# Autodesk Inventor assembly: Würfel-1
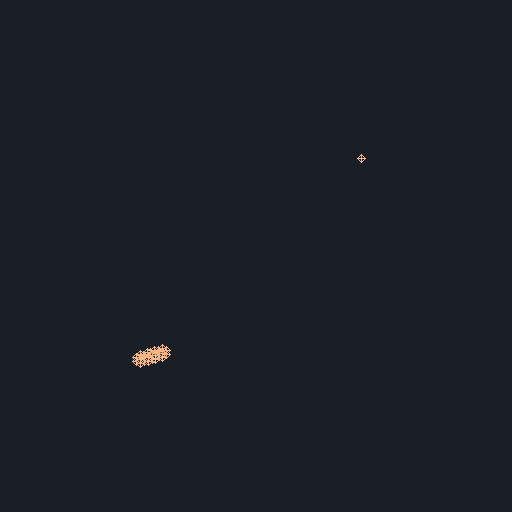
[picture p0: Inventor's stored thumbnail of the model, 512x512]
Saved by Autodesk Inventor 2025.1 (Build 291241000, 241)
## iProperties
Company: Ed. Züblin AG
Created: 2021-07
Part Number: Würfel-1
Material: Stahlbeton C30/37
Document SubType Name: Assembly
Designer: Eimannsmir
Mass: 14.8261 g
Surface Area: 31.3494 cm^2
Volume: 5.93044 cm^3
Density: 2.5 g/cm^3
z_Bereich: Tunnelbau
z_Direktion: Tief- und Tunnelbau
z_Konzerneinheit: Zentrale Technik
cpiComponentType: Attribut
cpiFitMatchkey: =<z_Matchkey>
z_Matchkey: =<z_Matchkey_010>_<z_Matchkey_020>_<z_Matchkey_030>_<z_Matchkey_040>_<z_Matchkey_050>_<z_Matchkey_060>_<z_Matchkey_070>_<z_Matchkey_080>_<z_Matchkey_090>_<z_Mat
z_Matchkey_010: xxxxx
z_Matchkey_020: 5DTUB
z_Matchkey_030: xxx
z_Matchkey_040: xxx
z_Matchkey_050: xxx
z_Matchkey_060: xxx
z_Matchkey_070: xxx
z_Matchkey_080: xxx
z_Matchkey_090: xxx
z_Matchkey_100: xxx
z_Matchkey_110: xxx
z_Matchkey_120: xxxxxxx
z_Matchkey_130: xxxx
z_Matchkey_140: xxxx
DocNumber: Würfel-1.iam
Folder: Übung\
VDS_Category: Konstruktion
Koordinate x - Ursprung: 0.0
Koordinate y - Ursprung: 0.0
Koordinate z - Ursprung: 0.0
Rotation - z-Achse: 0.0
Betondeckung: ND
Betonstahlguete: ND
Bewehrungsgehalt: ND
Druckfestigkeitsklasse: ND
Expositionsklasse_X: ND
Expositionsklasse_XA: ND
Expositionsklasse_XC: ND
Expositionsklasse_XD: ND
Expositionsklasse_XF: ND
Expositionsklasse_XM: ND
Expositionsklasse_XS: ND
Feuchtigkeitsklasse: ND
Groesstkorn: ND
Herstellungsort: ND
Luftporenbeton: ND
Rohdichte: ND
Sichtbetonklasse: ND
Unbewehrter_Beton: ND
Wasserzementwert_max: ND
WU_Beton: ND
Zusatzmittel: ND
010_Eigentuemer: ND
020_Autor: ND
030_Projektnummer: ND
040_Bereich: ND
050_Vertragspartner: ND
060_Gewerk: ND
070_Bauwerk: ND
080_Bauwerksnummer: ND
090_Bezeichnung: ND
100_Gruppe: ND
110_Element: ND
120_Elementtyp: ND
130_Identifikationsnummer: ND
140_Position_1: ND
150_Position_2: ND
160_PUID: ND
170_Hauptmaterialitaet: ND
171_Materialindikator_1: ND
172_Materialindikator_2: ND
Dicke: ND
Flaeche: ND
Streckenachse: ND
Streckenkilometer_Anfang: ND
Streckenkilometer_Ende: ND
Tunnelachse: ND
Tunnelmeter_Anfang: ND
Tunnelmeter_Ende: ND
4D_Vorgangs_ID: ND
Bauphase_Abgebrochen: ND
Bauphase_Erstellt: ND
Status: ND
Author: Eimannsmir
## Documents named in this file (2)
- C:\z_Vault\CAD\Übung\Würfel-1.iam
- C:\z_Vault\CAD\Übung\Würfel-1.ipt
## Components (4 placed, 1 different names)
1. Würfel-1:1
2. Würfel-1:2
3. Würfel-1:3
4. Würfel-1:4
